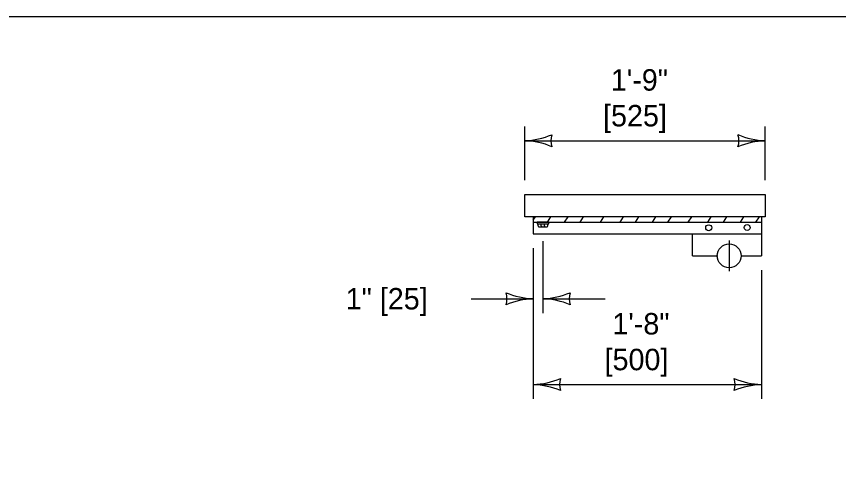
# Model space of a CAD drawing. Extents: x 49991.4 to 50021, y 49987.6 to 50011.4.
# Drawn here: x 50008.76 to 50011.058, y 49997.752 to 49998.999 of the extents above; entities that cross this region are included whole.
import ezdxf

# ---------------------------------------------------------------- set-up
doc = ezdxf.new("R2010")
doc.units = 0
for name, color, linetype in [('Level 1', 7, 'Continuous'), ('Level 2', 7, 'Continuous'), ('Level 3', 7, 'Continuous'), ('Level 5', 7, 'Continuous')]:
    doc.layers.add(name, color=color, linetype=linetype)

msp = doc.modelspace()

# ---------------------------------------------------------------- linework, layer by layer
at = {"layer": 'Level 1'}
for p, q in [((50010.2045, 49998.4293), (50010.2106, 49998.4384)), ((50010.2045, 49998.4375), (50010.2045, 49998.3912)), ((50010.2442, 49998.4243), (50010.2537, 49998.4384)), ((50010.2922, 49998.4243), (50010.3017, 49998.4384)), ((50010.3353, 49998.4243), (50010.3449, 49998.4384)), ((50010.3921, 49998.4243), (50010.4017, 49998.4384)), ((50010.4471, 49998.4243), (50010.4565, 49998.4384)), ((50010.4901, 49998.4243), (50010.4996, 49998.4384)), ((50010.5382, 49998.4243), (50010.5477, 49998.4384)), ((50010.5812, 49998.4243), (50010.5907, 49998.4384)), ((50010.638, 49998.4243), (50010.6475, 49998.4384)), ((50010.6929, 49998.4243), (50010.7024, 49998.4384)), ((50010.736, 49998.4243), (50010.7455, 49998.4384)), ((50010.784, 49998.4243), (50010.7935, 49998.4384)), ((50010.8272, 49998.4243), (50010.8367, 49998.4384)), ((50010.8425, 49998.4384), (50010.8425, 49998.3298)), ((50010.2045, 49998.4243), (50010.7172, 49998.4243)), ((50010.2179, 49998.4133), (50010.2179, 49998.4196)), ((50010.2205, 49998.4107), (50010.2431, 49998.4107)), ((50010.2271, 49998.4132), (50010.2271, 49998.4196)), ((50010.2363, 49998.4132), (50010.2363, 49998.4196)), ((50010.2456, 49998.4133), (50010.2456, 49998.4196)), ((50010.7172, 49998.4243), (50010.8425, 49998.4243)), ((50010.784, 49998.4243), (50010.8425, 49998.4243)), ((50010.2045, 49998.3911), (50010.65, 49998.3911)), ((50010.65, 49998.3298), (50010.65, 49998.3911)), ((50010.65, 49998.3911), (50010.784, 49998.3911)), ((50010.784, 49998.3911), (50010.8425, 49998.3911)), ((50010.65, 49998.3298), (50010.7206, 49998.3298)), ((50010.7858, 49998.3298), (50010.8425, 49998.3298))]:
    msp.add_line(p, q, dxfattribs=at)
for points in [[(49999.3835, 49998.9992), (50016.7501, 49998.9992), (50016.7501, 49987.7988), (49999.3835, 49987.7988)], [(50010.8529, 49998.5017), (50010.8529, 49998.4384), (50010.1806, 49998.4384), (50010.1806, 49998.5017)], [(50010.2152, 49998.4243), (50010.2152, 49998.4196), (50010.248, 49998.4196), (50010.248, 49998.4243)]]:
    msp.add_lwpolyline(points, close=True, dxfattribs=at)
for centre, radius in [((50010.6952, 49998.4082), 0.00843), ((50010.8026, 49998.4089), 0.00843), ((50010.7522, 49998.3298), 0.0333)]:
    msp.add_circle(centre, radius, dxfattribs=at)
for centre, start, end in [((50010.2205, 49998.4133), 180, 270), ((50010.2246, 49998.4133), 270, 0), ((50010.2298, 49998.4133), 180, 270), ((50010.2338, 49998.4133), 270, 0), ((50010.239, 49998.4133), 180, 270), ((50010.243, 49998.4133), 270, 0)]:
    msp.add_arc(centre, 0.00257, start, end, dxfattribs=at)
at = {"layer": 'Level 3'}
for p, q in [((50010.1806, 49998.5417), (50010.1806, 49998.6917)), ((50010.8529, 49998.5417), (50010.8529, 49998.6917)), ((50010.1806, 49998.6517), (50010.8529, 49998.6517)), ((50010.2318, 49998.1698), (50010.2318, 49998.3707)), ((50010.2045, 49998.3511), (50010.2045, 49997.9298)), ((50010.8425, 49998.2898), (50010.8425, 49997.9298)), ((50010.0311, 49998.2098), (50010.2045, 49998.2098)), ((50010.2318, 49998.2098), (50010.4052, 49998.2098)), ((50010.205, 49997.9698), (50010.8425, 49997.9698))]:
    msp.add_line(p, q, dxfattribs=at)
for centre, radius, start, end in [((50010.1692, 49998.8844), 0.233, 272.8273, 292.0772), ((50010.3089, 49998.6517), 0.0548, 162.1388, 197.8612), ((50010.8621, 49998.8739), 0.2223, 247.456, 267.6395), ((50010.7247, 49998.6517), 0.0548, 342.1388, 17.8612), ((50010.1715, 49998.4296), 0.2223, 67.456, 87.6395), ((50010.8644, 49998.419), 0.233, 92.8273, 112.0772), ((50010.2137, 49998.432), 0.2223, 247.456, 267.6395), ((50010.0763, 49998.2098), 0.0548, 342.1388, 17.8612), ((50010.2204, 49998.4425), 0.233, 272.8273, 292.0772), ((50010.3601, 49998.2098), 0.0548, 162.1388, 197.8612), ((50010.216, 49997.9771), 0.233, 92.8273, 112.0772), ((50010.2227, 49997.9877), 0.2223, 67.456, 87.6395), ((50010.1931, 49998.2025), 0.233, 272.8273, 292.0772), ((50010.1954, 49997.7477), 0.2223, 67.456, 87.6395), ((50010.3328, 49997.9698), 0.0548, 162.1388, 197.8612), ((50010.8517, 49998.192), 0.2223, 247.456, 267.6395), ((50010.7143, 49997.9698), 0.0548, 342.1388, 17.8612), ((50010.854, 49997.7371), 0.233, 92.8273, 112.0772)]:
    msp.add_arc(centre, radius, start, end, dxfattribs=at)
at = {"layer": 'Level 5'}
msp.add_line((50010.7521, 49998.373), (50010.7521, 49998.2865), dxfattribs=at)

# ---------------------------------------------------------------- texts
at = {"layer": 'Level 2'}
for s, p in [('1\'-9"', (50010.4214, 49998.7917)), ('[525]', (50010.3997, 49998.6917)), ('1" [25]', (50009.6801, 49998.1798)), ('1\'-8"', (50010.4257, 49998.1098)), ('[500]', (50010.4039, 49998.0098))]:
    msp.add_text(s, height=0.06, dxfattribs=at).set_placement(p)

doc.saveas('drawing.dxf')
